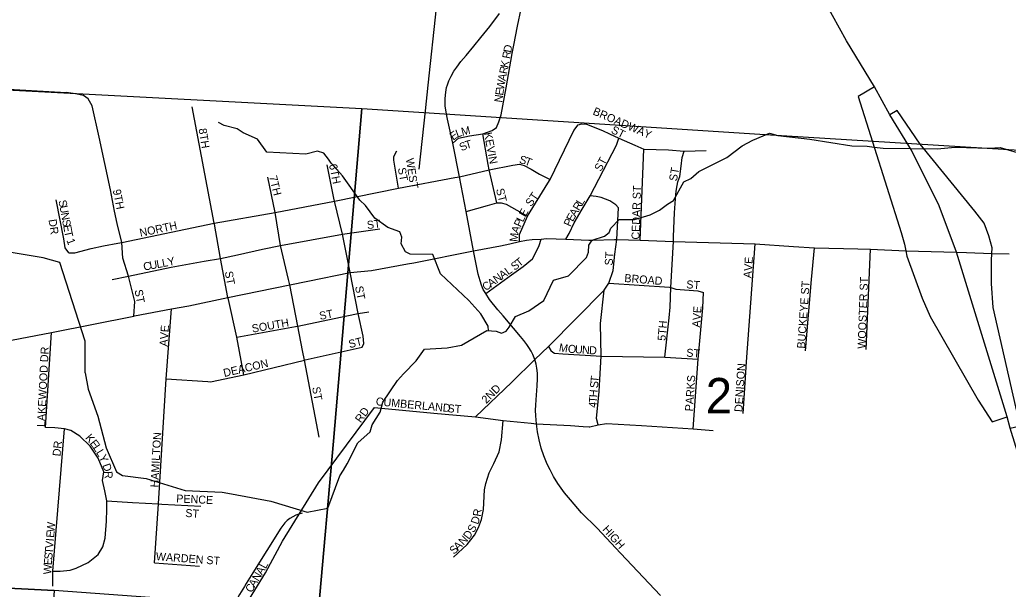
# Model space of a CAD drawing. Extents: x 0 to 40.4, y 0 to 22.
# Drawn here: x 6.04 to 7.209, y 16.73 to 17.403 of the extents above; entities that cross this region are included whole.
import ezdxf

# ---------------------------------------------------------------- set-up
doc = ezdxf.new("R2010")
doc.units = 0
for name, color, linetype in [('GM_X_City_Street', 7, 'Continuous'), ('GM_X_City_Street_Text', 7, 'Continuous'), ('GM_X_Interchange_Ramps', 7, 'Continuous'), ('GM_X_Minor_River', 7, 'Continuous'), ('GM_X_Rail_Line', 7, 'Continuous'), ('GM_X_Section', 7, 'Continuous'), ('GM_X_Section_Text', 7, 'Continuous'), ('GM_X_State_Route', 7, 'Continuous'), ('GM_X_US_Route', 7, 'Continuous'), ('SH_Data', 7, 'Continuous')]:
    doc.layers.add(name, color=color, linetype=linetype)

msp = doc.modelspace()

# ---------------------------------------------------------------- linework, layer by layer
at = {"layer": 'GM_X_City_Street'}
for points in [[(6.5873, 17.2683), (6.5928, 17.2701), (6.5985, 17.2723), (6.6035, 17.2756), (6.6063, 17.2824), (6.609, 17.2908), (6.6149, 17.3224), (6.6223, 17.3633), (6.6243, 17.3729), (6.6285, 17.3955), (6.6328, 17.416), (6.6357, 17.4318), (6.6371, 17.4432), (6.6385, 17.4644)], [(6.5765, 17.1296), (6.5676, 17.1765), (6.5599, 17.2175), (6.5519, 17.257), (6.5455, 17.2854), (6.5439, 17.2938), (6.543, 17.3014), (6.543, 17.31), (6.5435, 17.3176), (6.5446, 17.3231), (6.5455, 17.3262), (6.5472, 17.331), (6.5499, 17.3365), (6.5533, 17.3422), (6.5567, 17.3472), (6.5615, 17.3539), (6.5677, 17.361), (6.5766, 17.3719), (6.5851, 17.3822), (6.5956, 17.3952), (6.607, 17.4105)], [(5.6433, 17.3429), (6.0945, 17.3169)], [(6.1747, 17.0527), (6.1758, 17.07), (6.1683, 17.0999), (6.1616, 17.1213), (6.1605, 17.1397), (6.1548, 17.1622), (6.1517, 17.1769), (6.147, 17.2018), (6.1335, 17.2642), (6.1254, 17.3013), (6.1205, 17.3094), (6.115, 17.3134), (6.1055, 17.3156), (6.0945, 17.3169)], [(6.27, 17.1615), (6.2698, 17.1626), (6.2434, 17.3002)], [(6.6645, 17.2099), (6.6672, 17.2143), (6.6951, 17.2723), (6.7004, 17.279)], [(6.7004, 17.279), (6.7046, 17.2801), (6.7102, 17.2798), (6.7291, 17.2721), (6.7374, 17.2683)], [(6.5519, 17.257), (6.5585, 17.263), (6.5718, 17.2659), (6.5873, 17.2683)], [(6.5938, 17.2319), (6.5873, 17.2683)], [(6.6858, 17.1435), (6.6894, 17.1502), (6.6956, 17.1628), (6.7049, 17.179), (6.7143, 17.195), (6.7456, 17.2547), (6.7485, 17.2631)], [(6.7374, 17.2683), (6.7485, 17.2631), (6.7673, 17.2547), (6.778, 17.2502), (6.8069, 17.2493), (6.8256, 17.2478), (6.8518, 17.2483)], [(6.4877, 17.2038), (6.4821, 17.237), (6.4823, 17.2415), (6.4857, 17.2481)], [(6.7737, 17.1425), (6.778, 17.2502)], [(6.8131, 17.1468), (6.8141, 17.1748), (6.8156, 17.1967), (6.8166, 17.2027), (6.8183, 17.2114), (6.8206, 17.2179), (6.8219, 17.23), (6.8233, 17.24), (6.8256, 17.2478)], [(6.4111, 17.1922), (6.4033, 17.2316)], [(6.5543, 17.2164), (6.5599, 17.2175), (6.5949, 17.2255), (6.623, 17.2313), (6.631, 17.2322), (6.6362, 17.2306), (6.6447, 17.2262), (6.6543, 17.2203), (6.6672, 17.2143)], [(6.604, 17.1867), (6.5949, 17.2255), (6.5938, 17.2319)], [(6.1558, 17.1388), (6.1605, 17.1397), (6.2698, 17.1626), (6.3417, 17.175), (6.4119, 17.1886), (6.4877, 17.2038), (6.5543, 17.2164)], [(6.3576, 17.096), (6.3481, 17.1363), (6.3417, 17.175), (6.3331, 17.2171)], [(6.6307, 17.1408), (6.6307, 17.149), (6.6404, 17.1707), (6.6645, 17.2099)], [(6.0977, 17.1273), (6.0935, 17.1333), (6.0919, 17.1438), (6.0828, 17.1902)], [(6.4448, 17.0159), (6.4467, 17.0202), (6.4459, 17.029), (6.4401, 17.0558), (6.4305, 17.104), (6.4215, 17.1496), (6.4119, 17.1886), (6.4111, 17.1922)], [(6.7459, 17.1433), (6.7478, 17.1808), (6.7447, 17.1843), (6.7375, 17.1888), (6.7275, 17.1927), (6.7216, 17.1942), (6.7143, 17.195)], [(6.5676, 17.1765), (6.593, 17.1833), (6.604, 17.1867), (6.6092, 17.1865), (6.615, 17.1849), (6.6404, 17.1707)], [(6.2864, 17.0722), (6.2859, 17.0745), (6.2772, 17.1208), (6.27, 17.1615)], [(6.3267, 17.1316), (6.3481, 17.1363), (6.4215, 17.1496), (6.4655, 17.1557)], [(6.5789, 16.9336), (6.6216, 16.9744), (6.6488, 17.0011), (6.665, 17.0168), (6.731, 17.0834), (6.7365, 17.0916), (6.7416, 17.1067), (6.7436, 17.1258), (6.7459, 17.1433)], [(6.6215, 17.1014), (6.6353, 17.1114), (6.6463, 17.1205), (6.6506, 17.1287), (6.654, 17.136), (6.6563, 17.1436)], [(6.8026, 17.0041), (6.8077, 17.0504), (6.809, 17.0632), (6.8099, 17.0866), (6.8129, 17.1408), (6.8131, 17.1468)], [(6.0977, 17.1273), (6.1049, 17.1273), (6.1242, 17.1325), (6.1386, 17.1357), (6.1558, 17.1388)], [(6.2971, 17.1252), (6.3267, 17.1316)], [(6.8981, 16.9795), (6.8993, 16.9984), (6.9097, 17.138)], [(6.9764, 17.0959), (6.9796, 17.1333)], [(7.0409, 17.0132), (7.0461, 17.1316)], [(6.2576, 17.1174), (6.2772, 17.1208), (6.2971, 17.1252)], [(6.7977, 16.7222), (6.7501, 16.772), (6.7228, 16.8018), (6.7042, 16.8199), (6.6911, 16.8352), (6.684, 16.8437), (6.676, 16.8545), (6.6712, 16.8629), (6.6669, 16.8707), (6.6635, 16.8775), (6.6594, 16.8873), (6.6566, 16.8964), (6.6539, 16.9063), (6.6523, 16.9158), (6.651, 16.9253), (6.6501, 16.9346), (6.6499, 16.9413), (6.6502, 16.9471), (6.6504, 16.9536), (6.6518, 16.9703), (6.6523, 16.9784), (6.6523, 16.9852), (6.6514, 16.9911), (6.6504, 16.9956), (6.6488, 17.0011), (6.6464, 17.0071), (6.6445, 17.011), (6.6418, 17.0155), (6.6394, 17.0191), (6.636, 17.0237), (6.6318, 17.0286), (6.6238, 17.0383), (6.6114, 17.0531), (6.6051, 17.0602), (6.5955, 17.0721), (6.591, 17.0792), (6.5879, 17.084), (6.5859, 17.0892), (6.5842, 17.0943), (6.582, 17.1021), (6.5765, 17.1296)], [(6.149, 17.0959), (6.1683, 17.0999), (6.2186, 17.1106), (6.2576, 17.1174)], [(6.3741, 17.0121), (6.3686, 17.0408), (6.3592, 17.0894), (6.3576, 17.096)], [(6.591, 17.0792), (6.6215, 17.1014)], [(6.9691, 17.0117), (6.9764, 17.0959)], [(6.7365, 17.0916), (6.8081, 17.0868)], [(6.8081, 17.0868), (6.8099, 17.0866), (6.8158, 17.0843), (6.8419, 17.0825), (6.8484, 17.0807)], [(6.7238, 16.9241), (6.7219, 16.9315), (6.725, 16.9633), (6.726, 16.9777), (6.7274, 17.0053), (6.7265, 17.044), (6.731, 17.0834)], [(6.8364, 16.9193), (6.8421, 17.0016), (6.8478, 17.0622), (6.8484, 17.0807)], [(6.1992, 16.7609), (6.2036, 16.8304), (6.2129, 16.9784), (6.219, 17.0612)], [(6.3047, 16.9833), (6.2963, 17.0275), (6.2864, 17.0722)], [(6.3659, 17.0403), (6.3686, 17.0408), (6.4265, 17.0529)], [(6.4265, 17.0529), (6.4401, 17.0558), (6.4525, 17.0578)], [(6.2963, 17.0275), (6.3659, 17.0403)], [(6.0699, 16.9207), (6.0771, 17.0333)], [(6.3774, 17.0007), (6.4448, 17.0159)], [(6.665, 17.0168), (6.668, 17.012), (6.6703, 17.0099), (6.6724, 17.0088), (6.682, 17.0079), (6.7215, 17.0057)], [(6.3939, 16.9094), (6.3763, 17.0005), (6.3741, 17.0121)], [(6.7215, 17.0057), (6.7274, 17.0053), (6.8026, 17.0041), (6.8421, 17.0016)], [(6.2621, 16.9752), (6.2654, 16.975), (6.3047, 16.9833), (6.3763, 17.0005), (6.3774, 17.0007)], [(6.8955, 16.9372), (6.8981, 16.9795)], [(6.2129, 16.9784), (6.2621, 16.9752)], [(6.3019, 16.7029), (6.3302, 16.7491), (6.3505, 16.7865), (6.3929, 16.8555), (6.4592, 16.9443)], [(6.4592, 16.9443), (6.5293, 16.9376), (6.5789, 16.9336), (6.6116, 16.929), (6.6448, 16.9259)], [(6.0786, 16.7508), (6.0873, 16.7509), (6.0991, 16.7521), (6.1065, 16.7546), (6.1205, 16.7611), (6.1325, 16.7708), (6.1378, 16.7798), (6.1408, 16.7901), (6.1423, 16.8101), (6.1428, 16.8241), (6.1425, 16.834), (6.1403, 16.846), (6.1375, 16.8583), (6.1389, 16.8684), (6.1323, 16.8844), (6.123, 16.8987), (6.1108, 16.9107), (6.1002, 16.9173), (6.0924, 16.9193), (6.0812, 16.9205), (6.0699, 16.9207)], [(6.5529, 16.7676), (6.5689, 16.7823), (6.5776, 16.7936), (6.5824, 16.8025), (6.5859, 16.8121), (6.5881, 16.8239), (6.5894, 16.847), (6.5908, 16.8546), (6.5949, 16.8674), (6.6005, 16.8781), (6.6067, 16.8921), (6.6094, 16.9062), (6.6116, 16.929)], [(6.6448, 16.9259), (6.651, 16.9253), (6.6911, 16.923), (6.7062, 16.9221), (6.7133, 16.9218)], [(6.7133, 16.9218), (6.7142, 16.9218), (6.7238, 16.9241), (6.7338, 16.9254), (6.775, 16.923), (6.8364, 16.9193), (6.86, 16.9173)], [(6.0786, 16.7332), (6.0786, 16.7508), (6.0924, 16.9193)], [(6.1425, 16.834), (6.1729, 16.8322)], [(6.1729, 16.8322), (6.2036, 16.8304), (6.2076, 16.8301), (6.254, 16.8278)], [(6.1992, 16.7609), (6.2524, 16.7567)]]:
    msp.add_lwpolyline(points, dxfattribs=at)
at = {"layer": 'GM_X_Interchange_Ramps'}
for points in [[(7.0509, 17.3238), (7.0315, 17.3125), (7.0822, 17.1514), (7.0864, 17.1375), (7.0879, 17.1298)], [(7.1896, 17.1267), (7.1899, 17.1335), (7.1862, 17.1477), (7.1807, 17.1627), (7.1694, 17.1769), (7.1048, 17.2559), (7.0775, 17.2956), (7.0689, 17.2906)], [(7.0879, 17.1298), (7.0892, 17.1235), (7.107, 17.0739), (7.1168, 17.0521), (7.1736, 16.9533), (7.1899, 16.9274), (7.2077, 16.9333)], [(7.2113, 16.9201), (7.2232, 16.9228), (7.1912, 17.0626), (7.189, 17.0912), (7.189, 17.1031), (7.1893, 17.111), (7.1893, 17.1184), (7.1896, 17.1267)]]:
    msp.add_lwpolyline(points, dxfattribs=at)
at = {"layer": 'GM_X_Minor_River'}
for points in [[(6.5941, 17.0353), (6.5939, 17.0408), (6.5852, 17.0552), (6.5709, 17.0712), (6.5373, 17.1027), (6.5283, 17.1255), (6.5014, 17.1259), (6.4958, 17.1285), (6.4909, 17.138), (6.4916, 17.146), (6.4894, 17.1524), (6.475, 17.1574), (6.4595, 17.1684), (6.4486, 17.1836), (6.4418, 17.1897), (6.4215, 17.2185), (6.4082, 17.2334), (6.4049, 17.2383), (6.3992, 17.2455), (6.392, 17.2478), (6.378, 17.244), (6.3319, 17.2464), (6.321, 17.262), (6.304, 17.2692), (6.2968, 17.2741), (6.2813, 17.278), (6.2749, 17.2814)], [(6.117, 16.9856), (6.1207, 16.9662), (6.132, 16.9344), (6.1418, 16.8968), (6.1542, 16.8683), (6.161, 16.8642), (6.189, 16.8607), (6.2354, 16.8462), (6.2789, 16.8442), (6.2903, 16.8423), (6.3367, 16.8335), (6.3798, 16.8205), (6.404, 16.8254), (6.4181, 16.8637), (6.4226, 16.8705), (6.4268, 16.8777), (6.4397, 16.9027), (6.4541, 16.9159), (6.4564, 16.9239), (6.4659, 16.939), (6.4693, 16.9508), (6.4864, 16.9765), (6.4936, 16.9845), (6.5087, 16.9996), (6.5186, 17.0136), (6.5451, 17.0151), (6.5621, 17.0181), (6.592, 17.0355), (6.6033, 17.0347), (6.6094, 17.0324), (6.615, 17.0347), (6.6185, 17.0396), (6.626, 17.0521), (6.6419, 17.0589), (6.6594, 17.071), (6.6711, 17.0952), (6.6889, 17.1001), (6.7101, 17.1221), (6.7124, 17.1281), (6.7128, 17.1365), (6.7166, 17.1425), (6.7313, 17.1471), (6.737, 17.1516), (6.7389, 17.1565), (6.7488, 17.1667), (6.7669, 17.1667), (6.7855, 17.1724), (6.7964, 17.178), (6.8059, 17.1848), (6.8131, 17.1894), (6.8252, 17.2113), (6.8336, 17.2155), (6.843, 17.2238), (6.876, 17.2401), (6.8941, 17.254), (6.907, 17.2608), (6.9267, 17.2688), (6.9365, 17.2661), (6.9743, 17.2619), (7.0238, 17.2538), (7.042, 17.2534), (7.0503, 17.2526), (7.0612, 17.2511), (7.1251, 17.2506), (7.1463, 17.2524), (7.1864, 17.2512), (7.1993, 17.2519), (7.2291, 17.2435)], [(6.117, 16.9856), (6.117, 17.0228), (6.087, 17.1158), (6.0673, 17.1216), (6.0006, 17.1324)]]:
    msp.add_lwpolyline(points, dxfattribs=at)
at = {"layer": 'GM_X_Rail_Line'}
msp.add_lwpolyline([(6.512, 17.2264), (6.5195, 17.2953), (6.5227, 17.3257), (6.5327, 17.4171), (6.5419, 17.4918), (6.5467, 17.5503), (6.5515, 17.629), (6.5597, 17.7679), (6.5658, 17.8694), (6.5737, 18.0027)], dxfattribs=at)
at = {"layer": 'GM_X_Section'}
for points in [[(4.6284, 17.3961), (5.6266, 17.3411), (6.4444, 17.2982), (6.4106, 16.9046), (6.3929, 16.7053), (6.0805, 16.728), (5.57, 16.7542), (5.0349, 16.7787), (4.5943, 16.8006)], [(6.4444, 17.2982), (6.915, 17.2679), (7.3378, 17.2417), (7.2909, 16.6427), (7.1996, 16.6471), (6.6625, 16.6858), (6.3929, 16.7053), (6.4106, 16.9046)], [(6.0805, 16.728), (6.012, 15.7142), (5.5033, 15.7422), (5.57, 16.7542)]]:
    msp.add_lwpolyline(points, close=True, dxfattribs=at)
at = {"layer": 'GM_X_State_Route'}
for points in [[(7.1476, 17.1281), (7.1476, 17.1281), (7.1271, 17.1832), (7.0944, 17.2487), (7.0689, 17.2906), (7.0509, 17.3238), (7.0178, 17.378), (6.8436, 17.6932)], [(7.2747, 16.6438), (7.2755, 16.6702), (7.2751, 16.6952), (7.2696, 16.7262), (7.2587, 16.7671), (7.2113, 16.9201), (7.2077, 16.9333), (7.1476, 17.1281)]]:
    msp.add_lwpolyline(points, dxfattribs=at)
at = {"layer": 'GM_X_US_Route'}
for points in [[(6.4982, 17.1143), (6.5058, 17.1157), (6.5765, 17.1296), (6.6082, 17.1359), (6.6193, 17.1382), (6.6307, 17.1408), (6.6392, 17.1424), (6.6456, 17.1433), (6.6563, 17.1436), (6.6629, 17.1442), (6.6858, 17.1435), (6.7127, 17.1424), (6.7176, 17.1425)], [(6.7176, 17.1425), (6.7432, 17.1433), (6.7459, 17.1433), (6.7737, 17.1425), (6.8129, 17.1408), (6.9097, 17.138), (6.955, 17.135)], [(6.955, 17.135), (6.9796, 17.1333), (7.031, 17.132)], [(7.031, 17.132), (7.0461, 17.1316), (7.0879, 17.1298), (7.1476, 17.1281), (7.1596, 17.1277)], [(7.1596, 17.1277), (7.1896, 17.1267), (7.2102, 17.1261)], [(6.3805, 17.0938), (6.4305, 17.104), (6.4558, 17.1065), (6.4982, 17.1143)], [(6.1752, 17.0528), (6.219, 17.0612), (6.2395, 17.0648), (6.2859, 17.0745), (6.3592, 17.0894), (6.3805, 17.0938)], [(6.009, 17.0201), (6.0214, 17.0226), (6.0771, 17.0333), (6.1747, 17.0527), (6.1752, 17.0528)]]:
    msp.add_lwpolyline(points, dxfattribs=at)
at = {"layer": 'SH_Data'}
msp.add_line((6.3485, 16.8016), (6.3155, 16.749), dxfattribs=at)
for centre, radius, start, end in [((6.3821, 16.7805), 0.0398, 102.1535, 147.8861), ((7.2338, 16.1726), 1.0843, 147.8861, 151.0868)]:
    msp.add_arc(centre, radius, start, end, dxfattribs=at)

# ---------------------------------------------------------------- texts
at = {"layer": 'GM_X_City_Street_Text'}
for s, rotation, p in [('R', 78.8567, (6.6194, 17.3564)), ('D', 78.8723, (6.6208, 17.3637)), ('K', 78.8723, (6.6173, 17.3457)), ('R', 78.8567, (6.6159, 17.3384)), ('W', 79.7388, (6.6123, 17.3196)), ('A', 78.8915, (6.6143, 17.3302)), ('E', 81.7462, (6.6114, 17.3131)), ('N', 81.8421, (6.6102, 17.3048)), ('BROADWAY', 336.5995, (6.7167, 17.2914)), ('8TH', 279.0947, (6.2512, 17.274)), ('E', 35.6298, (6.5524, 17.26)), ('L', 20.0765, (6.5572, 17.2636)), ('M', 14.0362, (6.5632, 17.2658)), ('ST', 333.435, (6.7383, 17.2697)), ('T', 15.4612, (6.5679, 17.2501)), ('KEVIN', 280.7836, (6.5887, 17.2691)), ('S', 27.0537, (6.5625, 17.2473)), ('WEST', 278.9738, (6.4963, 17.2386)), ('S', 344.5125, (6.6298, 17.2338)), ('T', 338.8429, (6.636, 17.2321)), ('ST', 61.9343, (6.7271, 17.2229)), ('6TH', 281.7716, (6.4054, 17.2316)), ('ST', 280.6254, (6.4868, 17.2274)), ('ST', 79.9964, (6.8169, 17.2116)), ('7TH', 284.0363, (6.3345, 17.2175)), ('9TH', 281.3116, (6.1496, 17.2016)), ('ST', 284.0427, (6.6029, 17.2025)), ('CEDAR ST', 88.2911, (6.7727, 17.143)), ('S', 280.4896, (6.0854, 17.1891)), ('ST', 55.3092, (6.6447, 17.1814)), ('L', 59.2893, (6.7051, 17.183)), ('U', 280.4896, (6.0866, 17.1825)), ('E', 60.4889, (6.6377, 17.169)), ('A', 59.5123, (6.6971, 17.1694)), ('R', 59.3153, (6.7013, 17.1765)), ('DR', 278.9785, (6.0736, 17.1665)), ('N', 280.4896, (6.0881, 17.1743)), ('S', 280.4896, (6.0896, 17.1661)), ('ST', 7.12, (6.4509, 17.1555)), ('P', 65.097, (6.6322, 17.1571)), ('L', 64.7669, (6.635, 17.1631)), ('P', 65.2802, (6.6911, 17.1577)), ('E', 60.4889, (6.6938, 17.1636)), ('E', 280.4896, (6.0909, 17.1596)), ('T', 282.5117, (6.0921, 17.1527)), ('NORTH', 12.0093, (6.1824, 17.1463)), ('A', 68.4462, (6.6292, 17.1495)), ('1', 290.6003, (6.0947, 17.1424)), ('M', 85.2046, (6.6285, 17.1402)), ('L', 10.5749, (6.2088, 17.1105)), ('Y', 12.5132, (6.2157, 17.1118)), ('T', 38.8471, (6.6307, 17.1103)), ('ST', 86.4262, (6.741, 17.1122)), ('AVE', 86.0569, (6.9052, 17.0972)), ('C', 10.5525, (6.1867, 17.1063)), ('U', 10.5688, (6.194, 17.1077)), ('L', 10.5492, (6.2022, 17.1092)), ('L', 35.6042, (6.6174, 17.1008)), ('S', 35.5655, (6.6248, 17.1061)), ('ST', 280.6147, (6.2821, 17.1049)), ('A', 35.5677, (6.597, 17.0862)), ('N', 35.5758, (6.6038, 17.0911)), ('A', 35.5453, (6.6106, 17.0959)), ('BROAD', 355.3312, (6.7546, 17.093)), ('WOOSTER ST', 88.0237, (7.0402, 17.0138)), ('ST', 280.6279, (6.4362, 17.0874)), ('C', 35.5631, (6.5909, 17.0819)), ('ST', 356.4262, (6.8279, 17.0855)), ('BUCKEYE ST', 85.9621, (6.9685, 17.0139)), ('ST', 280.6279, (6.1754, 17.0832)), ('AVE', 85.9166, (6.8444, 17.0389)), ('SOUTH', 9.8702, (6.315, 17.033)), ('ST', 11.3043, (6.395, 17.048)), ('AVE', 86.0569, (6.2144, 17.0164)), ('5TH', 85.4202, (6.8035, 17.0231)), ('ST', 14.0427, (6.4299, 17.0146)), ('LAKEWOOD DR', 87.2224, (6.0694, 16.9213)), ('M', 350.0796, (6.6769, 17.0112)), ('O', 355.9957, (6.6878, 17.0094)), ('U', 356.3898, (6.6962, 17.0088)), ('N', 356.3691, (6.7045, 17.0083)), ('D', 356.6265, (6.7129, 17.0077)), ('ST', 356.4126, (6.8279, 17.0047)), ('DEACON', 13.0698, (6.2816, 16.9805)), ('DENISON', 86.2468, (6.8944, 16.9389)), ('T', 84.0882, (6.7241, 16.9737)), ('PARKS', 86.183, (6.836, 16.9397)), ('ST', 280.6147, (6.3854, 16.9682)), ('2ND', 45.0057, (6.5915, 16.9483)), ('S', 85.671, (6.7236, 16.9671)), ('CUMBERLAND', 354.6975, (6.4605, 16.9472)), ('T', 85.6788, (6.7223, 16.9497)), ('H', 85.6683, (6.7228, 16.9563)), ('RD', 53.7411, (6.443, 16.9256)), ('ST', 356.4254, (6.5454, 16.9389)), ('4', 85.6875, (6.7219, 16.9439)), ('K', 310.9001, (6.1165, 16.9082)), ('HAMILTON', 86.9077, (6.2035, 16.8497)), ('DR', 83.9946, (6.0877, 16.8864)), ('E', 307.5419, (6.1219, 16.902)), ('L', 303.584, (6.1258, 16.8969)), ('L', 301.3855, (6.1295, 16.8914)), ('Y', 295.1278, (6.1328, 16.886)), ('D', 289.2921, (6.1372, 16.8763)), ('R', 271.6518, (6.1398, 16.8692)), ('PENCE', 357.3938, (6.2246, 16.8322)), ('ST', 356.4118, (6.2352, 16.8151)), ('D', 71.9419, (6.5818, 16.8055)), ('R', 80.9883, (6.5848, 16.815)), ('W', 85.1009, (6.0807, 16.7967)), ('S', 61.0053, (6.5767, 16.7956)), ('HIGH', 311.4939, (6.7283, 16.7999)), ('E', 85.1011, (6.0802, 16.7901)), ('N', 47.4863, (6.5646, 16.7809)), ('D', 52.4246, (6.5708, 16.7877)), ('V', 85.0984, (6.0791, 16.7776)), ('I', 85.0984, (6.0798, 16.7859)), ('S', 43.8025, (6.5533, 16.7701)), ('A', 43.7943, (6.5581, 16.7747)), ('S', 85.0752, (6.078, 16.7643)), ('T', 85.1011, (6.0785, 16.771)), ('WARDEN ST', 355.7633, (6.2004, 16.7639)), ('W', 86.989, (6.0769, 16.7469)), ('E', 85.2409, (6.0774, 16.7577)), ('L', 61.6024, (6.3306, 16.753)), ('N', 59.064, (6.3219, 16.7382)), ('A', 60.2122, (6.3263, 16.7456)), ('C', 59.0654, (6.3138, 16.7247)), ('A', 59.0512, (6.3176, 16.7311))]:
    msp.add_text(s, height=0.00947, rotation=rotation, dxfattribs=at).set_placement(p)
at = {"layer": 'GM_X_Section_Text'}
msp.add_text('2', height=0.0419, rotation=0, dxfattribs=at).set_placement((6.8511, 16.9375))

doc.saveas('drawing.dxf')
